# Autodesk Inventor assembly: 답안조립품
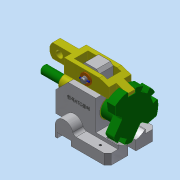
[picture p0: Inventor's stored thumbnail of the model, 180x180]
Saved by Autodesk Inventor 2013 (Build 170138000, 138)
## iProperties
Created: 2016-11
Part Number: 답안조립품
Document SubType Name: Assembly
Designer: Administrator
Author: Administrator
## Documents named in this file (8)
- C:\Users\Administrator\Desktop\461108V1005\답안조립품.iam
- C:\Users\Administrator\Desktop\461108V1005\답안본체.ipt
- C:\Users\Administrator\Desktop\461108V1005\부시.ipt
- C:\Users\Administrator\Desktop\461108V1005\분할대.ipt
- C:\Users\Administrator\Desktop\461108V1005\분할축.ipt
- C:\Users\Administrator\Desktop\461108V1005\와셔.ipt
- C:\Users\Administrator\Desktop\461108V1005\원통형핀.ipt
- C:\Users\Administrator\Desktop\461108V1005\클레비스핀.ipt
